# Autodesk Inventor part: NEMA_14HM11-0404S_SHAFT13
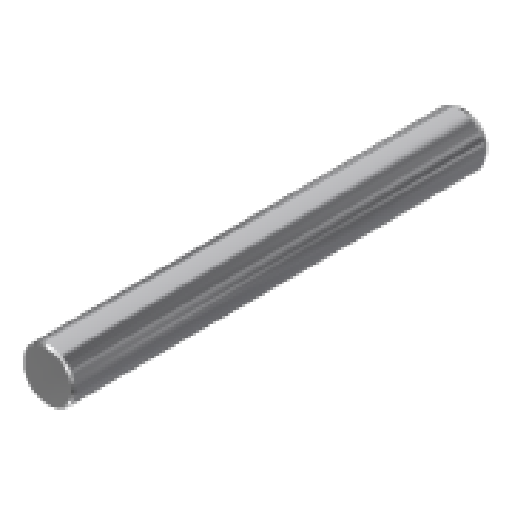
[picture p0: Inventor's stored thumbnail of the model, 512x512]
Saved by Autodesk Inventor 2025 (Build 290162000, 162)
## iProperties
Created: 2019-11
Part Number: NEMA_14HM11-0404S_SHAFT13
Material: Générique
Document SubType Name: Modeling
Designer: thoma
Density: 1 g/cm^3
Appearance: Aluminium - Plat
Author: thoma
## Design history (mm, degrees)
sketch "Esquisse1"
  geometry: C1 r 2.5 at (0, 0); 1 further point
  constraints: 1 centre point, 1 coincident
  dimensions: "d0" = 5 diameter of C1
extrude "Extrusion1" new body sketch "Esquisse1" distance "d1" = 40; taper "d2" = 0 deg
chamfer "Chanfrein1" distance "d3" = 0.2; stored, may be unused: second distance "d4" = 2, angle "d5" = 45 deg
chamfer "Chanfrein2" distance "d6" = 0.3; stored, may be unused: second distance "d7" = 2, angle "d8" = 60 deg
sketch "Esquisse2"
  geometry: L1 (-2.5, 0)-(2, 0); L2 (2, 0)-(2, 1.5); L3 (2, 0)-(2, -1.5); A1 r 2.5 centre (0, 0) between (2, -1.5) and (2, 1.5); 2 further points
  constraints: 6 end point, 2 point on circle, 1 centre point, 1 coincident, 1 horizontal, 1 horizontal alignment, 1 point on line, 1 vertical, 1 other
  dimensions: "d9" = 4.5 distance of L1.start L1.end
extrude "Extrusion2" cut sketch "Esquisse2" distance "d10" = 15; taper "d11" = 0 deg
fillet "Congé1" dims "d12" = 0.1
node "Solide1"
